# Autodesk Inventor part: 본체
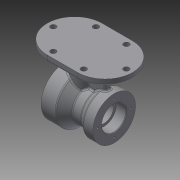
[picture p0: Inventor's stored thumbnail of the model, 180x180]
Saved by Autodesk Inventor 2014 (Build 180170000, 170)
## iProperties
Created: 2020-01
Part Number: 본체
Material: Generic
Document SubType Name: Modeling
Designer: kh
Density: 1 g/cm^3
Appearance: Default
Author: kh
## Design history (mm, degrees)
sketch "Sketch1"
  geometry: L1 (-25, 45)-(25, 45); L2 (25, 45)-(25, -45); L3 (25, -45)-(-25, -45); L4 (-25, -45)-(-25, 45); L5 (-25, 45)-(25, -45); L6 (25, 45)-(-25, -45); 3 further points
  constraints: 12 end point, 4 midpoint, 2 parallel, 2 vertical alignment, 1 horizontal, 1 perpendicular, 4 other
  dimensions: "d0" = 50 distance of L1.start L1.end; "d1" = 90 distance of L3.end L1.start
extrude "Extrusion1" new body sketch "Sketch1" distance "d2" = 10; taper "d3" = 0 deg
sketch "Sketch2"
  geometry: A1 r 45 centre (-25, 0) between (-25, 45) and (-25, -45) reference; A2 r 45 centre (25, 0) between (25, -45) and (25, 45) reference; A3 r 35 centre (-25, 0) between (-25, 35) and (-25, -35); A4 r 35 centre (25, 0) between (25, 35) and (60, 0); 3 further points
  constraints: 6 point on circle, 4 vertical alignment, 2 centre point, 2 coincident, 2 horizontal alignment
  dimensions: "d4" = 70 diameter of A3; "d5" = 70 diameter of A4
hole "Hole1" sketch "Sketch2" at (-25, 35), (25, 35), (60, 0), (25, -35), (-25, -35), (-60, 0) diameter "d6" = 9; stored, may be unused: countersink angle "d10" = 90 deg, drill point angle "d12" = 118 deg; dims "d7" = 6, "d8" = 4, "d9" = 2, "d11" = 8
sketch "Sketch3"
  geometry: L1 (25, 10)-(-25, 10) reference; L2 (0, 10)-(0, -70); L3 (70, 0)-(70, 10) reference; L4 (40, -70)-(40, -110); L5 (40, -110)-(16, -110); L6 (40, -70)-(-40, -70); L7 (-40, -70)-(-40, -105); L8 (-40, -105)-(-24, -105); L9 (1.103, -97.5)-(-13.289, -97.5); L10 (-24, -105)-(-13.289, -97.5); L11 (16, -110)-(1.103, -97.5); 1 further point
  constraints: 18 end point, 4 perpendicular, 3 parallel, 1 horizontal alignment, 1 midpoint
  dimensions: "d14" = 30 distance between parallel lines of L3 L4; "d15" = 40 distance of L4.start L4.end; "d16" = 24 distance of L4.end L5.end; "d17" = 80 distance of L4.start L6.end; "d18" = 35 distance of L6.end L7.end; "d19" = 16 distance of L7.end L8.end; "d20" = 55 diameter of L9 L6; "d21" = 40 deg angle of L9 L11; "d22" = 35 deg angle of L9 L10; "d23" = 80 distance of L2.start L2.end
revolve "Revolution1" sketch "Sketch3" stored, may be unused: angle "d24" = 90 deg
sketch "Sketch4"
  geometry: L1 (-25, -45)-(25, -45) reference; L2 (-40, 35)-(-40, -35) reference; L3 (-30, -5)-(-30, 5); L4 (-30, -5)-(8.593, -5); L5 (-30, 5)-(8.593, 5); L6 (8.593, 5)-(8.593, -5); C1 r 16 at (12, 0); A1 r 45 centre (25, 0) between (25, -45) and (25, 45) reference; 3 further points
  constraints: 8 end point, 2 parallel, 2 perpendicular, 1 centre point, 1 horizontal alignment, 1 midpoint, 1 point on circle
  dimensions: "d25" = 58 distance of point (70, 0) C1.centre; "d26" = 32 diameter of C1; "d27" = 10 distance of L3.start L3.end; "d28" = 45 distance from line of L1 C1.centre; "d29" = 10 distance between parallel lines of L3 L2
extrude "Extrusion2" join sketch "Sketch4" distance "d30" = 60; taper "d31" = 0 deg
sketch "Sketch5"
  geometry: C1 r 40 at (0, 0) reference; C2 r 26 at (0, 0); 1 further point
  constraints: 1 centre point, 1 coincident
  dimensions: "d32" = 52 diameter of C2
extrude "Extrusion3" cut sketch "Sketch5" distance "d33" = 20; taper "d34" = 0 deg
sketch "Sketch6"
  geometry: C1 r 35 at (0, 0) reference; C2 r 20 at (0, 0); 1 further point
  constraints: 1 centre point, 1 coincident
  dimensions: "d35" = 40 diameter of C2
extrude "Extrusion4" cut sketch "Sketch6" distance "d36" = 17; taper "d37" = 0 deg
sketch "Sketch7"
  geometry: C1 r 20 at (0, 0) reference; C2 r 16 at (0, 0); 1 further point
  constraints: 1 centre point, 1 coincident
  dimensions: "d38" = 32 diameter of C2
extrude "Extrusion5" cut sketch "Sketch7" distance "d39" = 60; taper "d40" = 0 deg
sketch "Sketch8" dims "d41" = 66
  geometry: C1 r 26 at (0, 0) reference; C2 r 40 at (0, 0) reference; 3 further points
  constraints: 2 horizontal alignment, 1 coincident, 2 other
hole "Hole2" sketch "Sketch8" at (-33, 0) diameter "d42" = 3.242; stored, may be unused: countersink angle "d46" = 90 deg, drill point angle "d48" = 118 deg; dims "d43" = 9, "d44" = 4, "d45" = 2, "d47" = 11
pattern_circular "Circular Pattern1" dims angle "d50" = 360 deg
sketch "Sketch9" dims "d52" = 55
  geometry: C1 r 20 at (0, 0) reference; C2 r 35 at (0, 0) reference; 3 further points
  constraints: 2 horizontal alignment, 1 coincident, 2 other
hole "Hole3" sketch "Sketch9" at (27.5, 0) diameter "d53" = 3.242; stored, may be unused: countersink angle "d57" = 90 deg, drill point angle "d59" = 118 deg; dims "d54" = 9, "d55" = 4, "d56" = 2, "d58" = 11
pattern_circular "Circular Pattern2" dims angle "d61" = 360 deg
fillet "Fillet1" dims "d63" = 0.3
fillet "Fillet2" dims "d64" = 3
fillet "Fillet3" dims "d65" = 3
fillet "Fillet4" dims "d66" = 3
chamfer "Chamfer1" distance "d67" = 1; stored, may be unused: second distance "d68" = 2, angle "d69" = 45 deg
sketch "Sketch10"
  geometry: L1 (50, 0)-(0, 0) reference; L2 (-45, 7)-(-45, 0) reference; 2 further points
  constraints: 1 other
  dimensions: "d70" = 4 distance from line of L1 point (25, 4); "d71" = 70 distance from line of L2 point (25, 4)
emboss "Emboss1" sketch "Sketch10" dims "d72" = 0.5, "d73" = 0
body "Solid1"
